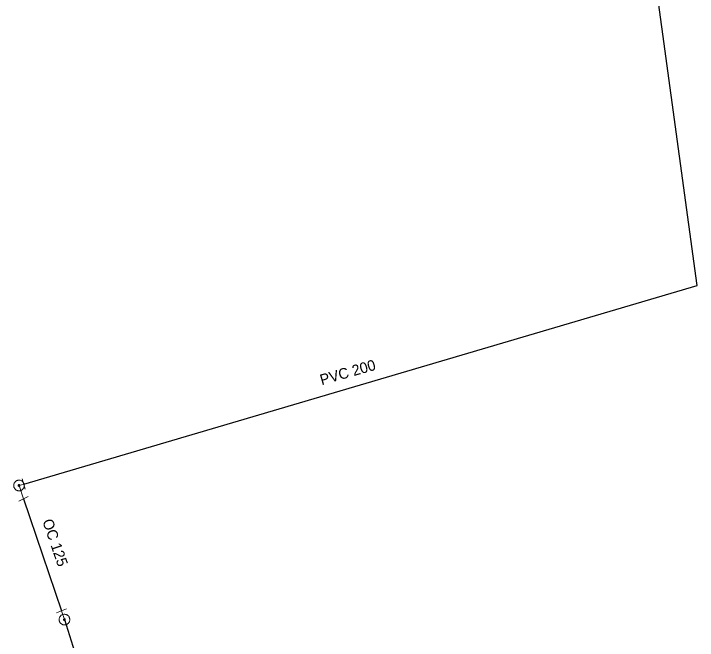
# Model space of a CAD drawing. Extents: x -807203 to -805207, y -993656 to -992505.
# Drawn here: x -807111.6 to -807047.6, y -993090.4 to -993031.7 of the extents above; entities that cross this region are included whole.
import ezdxf

# ---------------------------------------------------------------- set-up
doc = ezdxf.new("R2010")
doc.units = 0
doc.header["$LTSCALE"] = 0.4
for name, color, linetype, lineweight in [('1', 7, 'Continuous', 13), ('14', 7, 'Continuous', 25), ('17', 7, 'Continuous', 25), ('34', 7, 'Continuous', 13), ('47', 7, 'Continuous', 13)]:
    doc.layers.add(name, color=color, linetype=linetype, lineweight=lineweight)

msp = doc.modelspace()

# ---------------------------------------------------------------- linework, layer by layer
at = {"layer": '14', "lineweight": 13}
for p, q in [((-807110.708, -993075.809), (-807111.149, -993075.939)), ((-807111.149, -993075.939), (-807110.726, -993077.186)), ((-807107.17, -993087.673), (-807106.89, -993088.501))]:
    msp.add_line(p, q, dxfattribs=at)
at = {"layer": '17'}
for p, q in [((-807110.726, -993077.186), (-807107.17, -993087.673)), ((-807106.89, -993088.501), (-807104.484, -993096.025))]:
    msp.add_line(p, q, dxfattribs=at)
msp.add_lwpolyline([(-807110.708, -993075.809), (-807047.581, -993057.206), (-807051.701, -993027.227), (-807049.977, -993026.962)], dxfattribs=at)
at = {"layer": '34'}
for p, q in [((-807110.849, -993075.329), (-807110.567, -993076.288)), ((-807111.17, -993077.415), (-807110.281, -993076.957)), ((-807107.635, -993087.854), (-807106.703, -993087.492))]:
    msp.add_line(p, q, dxfattribs=at)
at = {"layer": '47'}
for points in [[(-807110.996, -993076.415), (-807110.947, -993076.396), (-807110.9, -993076.372), (-807110.857, -993076.344), (-807110.816, -993076.312), (-807110.778, -993076.274), (-807110.745, -993076.233), (-807110.717, -993076.19), (-807110.693, -993076.143), (-807110.674, -993076.095), (-807110.66, -993076.044), (-807110.651, -993075.992), (-807110.649, -993075.94), (-807110.651, -993075.888), (-807110.659, -993075.836), (-807110.672, -993075.786), (-807110.691, -993075.737), (-807110.715, -993075.69), (-807110.744, -993075.646), (-807110.775, -993075.606), (-807110.813, -993075.568), (-807110.854, -993075.535), (-807110.898, -993075.506), (-807110.944, -993075.482), (-807110.992, -993075.463), (-807111.043, -993075.45), (-807111.095, -993075.441), (-807111.147, -993075.438), (-807111.199, -993075.441), (-807111.251, -993075.449), (-807111.301, -993075.462), (-807111.35, -993075.481), (-807111.397, -993075.505), (-807111.441, -993075.533), (-807111.481, -993075.565), (-807111.519, -993075.603), (-807111.552, -993075.643), (-807111.581, -993075.687), (-807111.605, -993075.733), (-807111.624, -993075.782), (-807111.637, -993075.833), (-807111.646, -993075.885), (-807111.649, -993075.936), (-807111.646, -993075.989), (-807111.638, -993076.041), (-807111.625, -993076.091), (-807111.606, -993076.14), (-807111.582, -993076.187), (-807111.555, -993076.231), (-807111.522, -993076.271), (-807111.484, -993076.309), (-807111.444, -993076.342), (-807111.401, -993076.37), (-807111.354, -993076.394), (-807111.305, -993076.413), (-807111.254, -993076.427), (-807111.202, -993076.436), (-807111.151, -993076.438), (-807111.098, -993076.436), (-807111.046, -993076.428)], [(-807111.123, -993076.017), (-807111.115, -993076.014), (-807111.108, -993076.009), (-807111.101, -993076.005), (-807111.094, -993076), (-807111.088, -993075.994), (-807111.083, -993075.987), (-807111.077, -993075.98), (-807111.074, -993075.972), (-807111.071, -993075.964), (-807111.068, -993075.956), (-807111.067, -993075.947), (-807111.067, -993075.938), (-807111.067, -993075.93), (-807111.068, -993075.922), (-807111.07, -993075.913), (-807111.073, -993075.905), (-807111.078, -993075.898), (-807111.082, -993075.891), (-807111.087, -993075.884), (-807111.093, -993075.878), (-807111.1, -993075.873), (-807111.107, -993075.867), (-807111.115, -993075.864), (-807111.123, -993075.86), (-807111.131, -993075.858), (-807111.14, -993075.857), (-807111.149, -993075.857), (-807111.157, -993075.857), (-807111.165, -993075.858), (-807111.174, -993075.86), (-807111.182, -993075.863), (-807111.189, -993075.868), (-807111.196, -993075.872), (-807111.203, -993075.877), (-807111.209, -993075.883), (-807111.215, -993075.889), (-807111.22, -993075.897), (-807111.223, -993075.905), (-807111.227, -993075.913), (-807111.229, -993075.921), (-807111.23, -993075.93), (-807111.23, -993075.939), (-807111.23, -993075.947), (-807111.229, -993075.955), (-807111.227, -993075.964), (-807111.224, -993075.972), (-807111.219, -993075.979), (-807111.215, -993075.986), (-807111.21, -993075.993), (-807111.204, -993075.999), (-807111.198, -993076.005), (-807111.19, -993076.01), (-807111.182, -993076.013), (-807111.174, -993076.016), (-807111.166, -993076.019), (-807111.157, -993076.02), (-807111.148, -993076.02), (-807111.14, -993076.02), (-807111.132, -993076.019)], [(-807106.729, -993088.974), (-807106.681, -993088.955), (-807106.634, -993088.93), (-807106.592, -993088.901), (-807106.551, -993088.868), (-807106.514, -993088.831), (-807106.482, -993088.789), (-807106.454, -993088.745), (-807106.431, -993088.698), (-807106.413, -993088.65), (-807106.399, -993088.599), (-807106.392, -993088.547), (-807106.39, -993088.494), (-807106.393, -993088.442), (-807106.402, -993088.391), (-807106.416, -993088.34), (-807106.435, -993088.292), (-807106.46, -993088.245), (-807106.489, -993088.202), (-807106.522, -993088.162), (-807106.559, -993088.125), (-807106.601, -993088.093), (-807106.645, -993088.064), (-807106.692, -993088.041), (-807106.741, -993088.023), (-807106.791, -993088.01), (-807106.843, -993088.003), (-807106.896, -993088), (-807106.948, -993088.004), (-807106.999, -993088.013), (-807107.05, -993088.027), (-807107.098, -993088.046), (-807107.145, -993088.071), (-807107.189, -993088.099), (-807107.228, -993088.133), (-807107.265, -993088.17), (-807107.298, -993088.211), (-807107.326, -993088.255), (-807107.349, -993088.302), (-807107.367, -993088.352), (-807107.38, -993088.402), (-807107.387, -993088.454), (-807107.39, -993088.506), (-807107.386, -993088.559), (-807107.377, -993088.61), (-807107.363, -993088.661), (-807107.344, -993088.709), (-807107.319, -993088.756), (-807107.291, -993088.799), (-807107.257, -993088.839), (-807107.22, -993088.876), (-807107.179, -993088.909), (-807107.135, -993088.936), (-807107.088, -993088.959), (-807107.039, -993088.977), (-807106.988, -993088.991), (-807106.936, -993088.998), (-807106.884, -993089), (-807106.831, -993088.997), (-807106.78, -993088.988)], [(-807106.863, -993088.578), (-807106.855, -993088.575), (-807106.848, -993088.571), (-807106.841, -993088.566), (-807106.834, -993088.561), (-807106.828, -993088.555), (-807106.823, -993088.548), (-807106.818, -993088.541), (-807106.814, -993088.533), (-807106.812, -993088.525), (-807106.809, -993088.517), (-807106.808, -993088.508), (-807106.808, -993088.499), (-807106.808, -993088.491), (-807106.809, -993088.483), (-807106.812, -993088.474), (-807106.815, -993088.466), (-807106.819, -993088.459), (-807106.824, -993088.452), (-807106.829, -993088.445), (-807106.835, -993088.439), (-807106.842, -993088.434), (-807106.849, -993088.429), (-807106.857, -993088.425), (-807106.865, -993088.422), (-807106.873, -993088.42), (-807106.882, -993088.419), (-807106.891, -993088.419), (-807106.899, -993088.419), (-807106.907, -993088.42), (-807106.916, -993088.423), (-807106.924, -993088.426), (-807106.931, -993088.43), (-807106.938, -993088.435), (-807106.945, -993088.44), (-807106.951, -993088.446), (-807106.956, -993088.452), (-807106.961, -993088.46), (-807106.965, -993088.468), (-807106.968, -993088.476), (-807106.97, -993088.484), (-807106.971, -993088.493), (-807106.971, -993088.502), (-807106.971, -993088.51), (-807106.97, -993088.518), (-807106.967, -993088.527), (-807106.964, -993088.535), (-807106.96, -993088.542), (-807106.955, -993088.549), (-807106.95, -993088.556), (-807106.944, -993088.562), (-807106.938, -993088.567), (-807106.93, -993088.572), (-807106.922, -993088.576), (-807106.914, -993088.578), (-807106.906, -993088.581), (-807106.897, -993088.582), (-807106.888, -993088.582), (-807106.88, -993088.582), (-807106.872, -993088.581)]]:
    msp.add_lwpolyline(points, close=True, dxfattribs=at)

# ---------------------------------------------------------------- texts
at = {"layer": '1'}
for s, rotation, p in [('PVC 200 ', 16, (-807082.78, -993066.551)), ('OC 125', 289, (-807108.977, -993079.271))]:
    msp.add_text(s, height=1, rotation=rotation, dxfattribs=at).set_placement(p)

doc.saveas('drawing.dxf')
